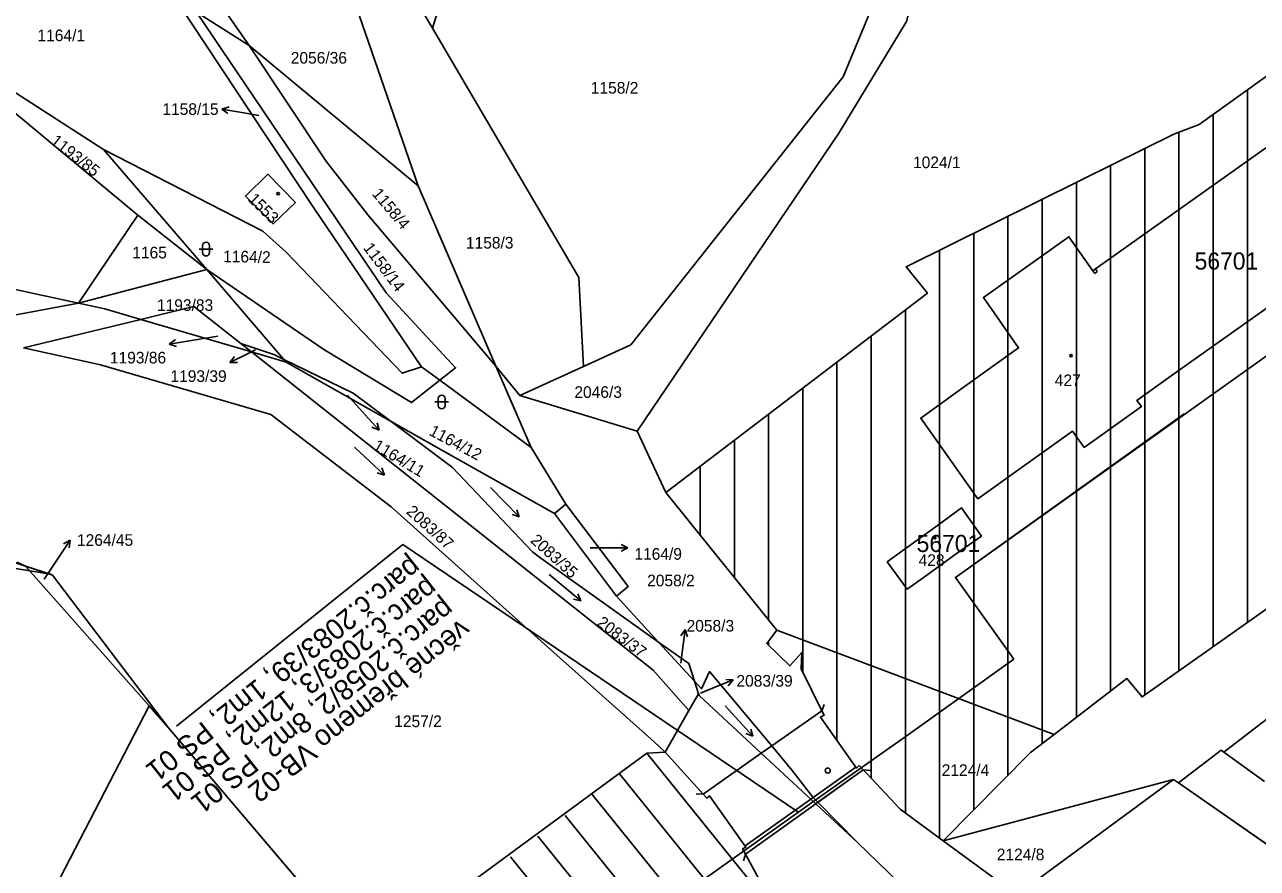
# Model space of a CAD drawing. Extents: x -794765 to -785424, y -1118958 to -1108731.
# Drawn here: x -792518 to -792337.7, y -1109962.1 to -1109838.8 of the extents above; entities that cross this region are included whole.
import ezdxf

# ---------------------------------------------------------------- set-up
doc = ezdxf.new("R2010")
doc.units = 0
for name, color, linetype in [('Level 66', 7, 'Continuous'), ('Level 75', 7, 'Continuous'), ('Level 76', 7, 'Continuous'), ('Level 77', 7, 'Continuous'), ('Level 78', 7, 'Continuous'), ('Level 79', 7, 'Continuous'), ('Level 80', 7, 'Continuous'), ('Level 81', 7, 'Continuous'), ('Vrstva 1', 7, 'Continuous'), ('Vrstva 53', 7, 'Continuous')]:
    doc.layers.add(name, color=color, linetype=linetype)

msp = doc.modelspace()

# ---------------------------------------------------------------- linework, layer by layer
at = {"layer": 'Level 66'}
for p, q in [((-792491.95, -1109871.12), (-792491.95, -1109872.12)), ((-792490.95, -1109872.12), (-792490.95, -1109871.12)), ((-792492.45, -1109871.62), (-792490.45, -1109871.62)), ((-792457.99, -1109893.95), (-792455.99, -1109893.95)), ((-792457.49, -1109893.45), (-792457.49, -1109894.45)), ((-792456.49, -1109894.45), (-792456.49, -1109893.45)), ((-792469.74, -1109900.54), (-792465.35, -1109904.63)), ((-792465.35, -1109904.63), (-792465.72, -1109903.6)), ((-792465.35, -1109904.63), (-792466.41, -1109904.33)), ((-792449.84, -1109906.43), (-792445.67, -1109910.75)), ((-792445.67, -1109910.75), (-792446.71, -1109910.39)), ((-792445.67, -1109910.75), (-792445.99, -1109909.7)), ((-792441.26, -1109919.17), (-792436.66, -1109923.03)), ((-792436.66, -1109923.03), (-792437.73, -1109922.78)), ((-792436.66, -1109923.03), (-792437.09, -1109922.01)), ((-792415.53, -1109938.35), (-792411.52, -1109942.81)), ((-792411.52, -1109942.81), (-792412.54, -1109942.42)), ((-792411.52, -1109942.81), (-792411.8, -1109941.75))]:
    msp.add_line(p, q, dxfattribs=at)
for centre, start, end in [((-792491.45, -1109871.12), 0, 180), ((-792491.45, -1109872.12), 180, 359.9879), ((-792456.99, -1109893.45), 0, 180), ((-792456.99, -1109894.45), 180, 359.9879)]:
    msp.add_arc(centre, 0.5, start, end, dxfattribs=at)
at = {"layer": 'Level 75'}
for p, q in [((-792470.06, -1109834.57), (-792460.44, -1109862.36)), ((-792458.34, -1109839.35), (-792461.61, -1109833.78)), ((-792501.44, -1109866.68), (-792535.33, -1109838.48)), ((-792485.15, -1109841.88), (-792492.83, -1109837.02)), ((-792460.44, -1109862.36), (-792485.15, -1109841.88)), ((-792506.45, -1109857.05), (-792491.34, -1109874.62)), ((-792460.44, -1109862.36), (-792449.06, -1109888.71)), ((-792510.07, -1109879.52), (-792501.44, -1109866.68)), ((-792491.34, -1109874.62), (-792501.44, -1109866.68)), ((-792551.16, -1109870.68), (-792510.07, -1109879.52)), ((-792510.07, -1109879.52), (-792491.34, -1109874.62)), ((-792491.34, -1109874.62), (-792480.06, -1109887.74)), ((-792518.11, -1109886.06), (-792500.99, -1109881.89)), ((-792500.99, -1109881.89), (-792484.82, -1109886.64)), ((-792486.38, -1109885.41), (-792484.82, -1109886.64)), ((-792484.82, -1109886.64), (-792479.72, -1109888.14)), ((-792479.72, -1109888.14), (-792480.06, -1109887.74)), ((-792479.72, -1109888.14), (-792464.39, -1109896.81)), ((-792459.92, -1109888.82), (-792457.26, -1109890.78)), ((-792449.06, -1109888.71), (-792445.59, -1109893)), ((-792449.06, -1109888.71), (-792443.92, -1109900.63)), ((-792445.59, -1109893), (-792436.24, -1109888.75)), ((-792457.26, -1109890.78), (-792443.92, -1109900.63)), ((-792445.59, -1109893), (-792428.41, -1109898.21)), ((-792428.41, -1109898.21), (-792424.2, -1109907.16)), ((-792443.92, -1109900.63), (-792438.83, -1109908.9)), ((-792407.99, -1109927.32), (-792424.2, -1109907.16)), ((-792438.83, -1109908.9), (-792440.51, -1109910.24)), ((-792440.51, -1109910.24), (-792431.42, -1109922.33)), ((-792519.12, -1109917.38), (-792517.82, -1109917.95)), ((-792499.77, -1109938.38), (-792517.82, -1109917.95)), ((-792431.42, -1109922.33), (-792425.28, -1109929.04)), ((-792407.99, -1109927.32), (-792367.46, -1109942.54)), ((-792425.28, -1109929.04), (-792420.03, -1109934.77)), ((-792420.03, -1109934.77), (-792419.43, -1109936.6)), ((-792419.43, -1109936.6), (-792420.84, -1109939.05)), ((-792525.39, -1109987.79), (-792499.77, -1109938.38)), ((-792499.77, -1109938.38), (-792496.95, -1109941.57)), ((-792420.84, -1109939.05), (-792424.33, -1109945.11)), ((-792496.95, -1109941.57), (-792468.07, -1109975.45)), ((-792394.9, -1109948.21), (-792395.36, -1109947.72)), ((-792383.68, -1109958.07), (-792350, -1109949.1)), ((-792350, -1109949.1), (-792372.92, -1109965.97)), ((-792349.29, -1109949.6), (-792350, -1109949.1)), ((-792349.29, -1109949.6), (-792300.79, -1109983.35)), ((-792372.92, -1109965.97), (-792383.68, -1109958.07))]:
    msp.add_line(p, q, dxfattribs=at)
for points in [[(-792436.24, -1109888.75), (-792429.34, -1109885.63), (-792398.28, -1109846.46), (-792394.13, -1109836.46), (-792388.49, -1109812.75), (-792381.95, -1109813.67)], [(-792485.15, -1109841.88), (-792494.43, -1109828.49), (-792506.9, -1109817.42)], [(-792444.99, -1109826.89), (-792455.12, -1109834.05), (-792456.58, -1109835.43), (-792457.64, -1109837.14), (-792458.34, -1109839.35)], [(-792386.68, -1109829.15), (-792389.02, -1109838.35), (-792398.94, -1109854.66), (-792428.41, -1109898.21)], [(-792459.92, -1109888.82), (-792475.83, -1109865.41), (-792495.87, -1109835.1)], [(-792535.33, -1109838.48), (-792529.02, -1109842.55), (-792506.45, -1109857.05)], [(-792492.83, -1109837.02), (-792465.09, -1109878), (-792454.96, -1109888.96), (-792457.26, -1109890.78)], [(-792458.34, -1109839.35), (-792436.95, -1109875.77), (-792436.24, -1109888.75)], [(-792424.2, -1109907.16), (-792385.97, -1109878.06), (-792389.09, -1109874.23), (-792363.55, -1109861.57), (-792349.96, -1109854.83), (-792346.23, -1109853.43), (-792326.43, -1109839.17)], [(-792485.15, -1109841.88), (-792473.92, -1109858.72), (-792467.78, -1109866.63), (-792449.06, -1109888.71)], [(-792350.32, -1109890.12), (-792310.53, -1109861.95), (-792321.58, -1109846.27), (-792361.41, -1109874.49), (-792361.79, -1109874.77), (-792365.28, -1109869.81), (-792377.79, -1109878.69), (-792372.64, -1109886.06), (-792380.76, -1109891.84), (-792386.94, -1109896.32), (-792378.6, -1109908.09), (-792372.63, -1109903.82), (-792364.77, -1109898.2), (-792363.05, -1109900.6), (-792354.69, -1109894.62), (-792355.34, -1109893.72), (-792350.32, -1109890.12)], [(-792506.45, -1109857.05), (-792483.14, -1109869.01), (-792479.72, -1109872.05), (-792462.76, -1109889.76), (-792459.92, -1109888.82)], [(-792478.36, -1109864.79), (-792482.43, -1109860.67), (-792485.69, -1109863.88), (-792481.62, -1109867.94), (-792478.36, -1109864.79)], [(-792510.07, -1109879.52), (-792529.74, -1109883.15), (-792549.88, -1109872.57), (-792551.16, -1109870.68)], [(-792491.34, -1109874.62), (-792474.22, -1109886.31), (-792461.4, -1109894.05), (-792457.26, -1109890.78)], [(-792510.07, -1109879.52), (-792506.25, -1109880.34), (-792500.99, -1109881.89)], [(-792500.99, -1109881.89), (-792498.62, -1109881.31), (-792493.21, -1109880), (-792486.38, -1109885.41)], [(-792367.46, -1109942.54), (-792356.82, -1109934.38), (-792354.59, -1109937.05), (-792274.06, -1109880.18), (-792264.32, -1109887.25)], [(-792480.06, -1109887.74), (-792481.52, -1109887.04), (-792486.38, -1109885.41)], [(-792424.33, -1109945.11), (-792425.94, -1109943.64), (-792440.58, -1109930.57), (-792464.4, -1109909.3), (-792481.97, -1109895.81), (-792506.88, -1109888.52), (-792518.11, -1109886.06)], [(-792484.82, -1109886.64), (-792426.08, -1109933.16), (-792420.84, -1109939.05)], [(-792464.39, -1109896.81), (-792469.93, -1109892.67), (-792480.06, -1109887.74)], [(-792464.39, -1109896.81), (-792455.39, -1109903.53), (-792443.7, -1109915.86), (-792442.51, -1109916.76), (-792425.28, -1109929.04)], [(-792440.51, -1109910.24), (-792453.09, -1109903.18), (-792457.76, -1109900.56), (-792464.39, -1109896.81)], [(-792431.42, -1109922.33), (-792429.71, -1109920.9), (-792438.83, -1109908.9)], [(-792386.62, -1109919.63), (-792381.57, -1109916.02), (-792378.09, -1109913.54), (-792380.99, -1109909.44), (-792384.51, -1109912), (-792389.55, -1109915.67), (-792391.84, -1109917.33), (-792388.96, -1109921.29), (-792386.62, -1109919.63)], [(-792517.82, -1109917.95), (-792513.88, -1109919.24), (-792496.95, -1109941.57)], [(-792395.36, -1109947.72), (-792395.96, -1109947.08), (-792396.36, -1109947.46), (-792401.63, -1109940.01), (-792401.09, -1109939.74), (-792401.42, -1109939.07), (-792404.43, -1109932.95), (-792404.35, -1109930.54), (-792406.09, -1109932.53), (-792409.46, -1109929.26), (-792407.99, -1109927.32)], [(-792425.28, -1109929.04), (-792420.88, -1109932.17), (-792420.03, -1109934.77)], [(-792325.83, -1109932.23), (-792337.77, -1109941.39), (-792342.64, -1109945.14), (-792343.04, -1109944.85), (-792349.29, -1109949.6)], [(-792420.03, -1109934.77), (-792419.01, -1109935.88), (-792417.84, -1109933.35), (-792408.74, -1109944.21), (-792405.73, -1109947.8), (-792402.71, -1109951.72), (-792401.99, -1109952.45), (-792396.21, -1109958.32)], [(-792396.21, -1109958.32), (-792402.3, -1109952.67), (-792410.26, -1109945.28), (-792419.34, -1109936.86), (-792419.43, -1109936.6)], [(-792383.68, -1109958.07), (-792370.89, -1109945.17), (-792367.46, -1109942.54)], [(-792424.33, -1109945.11), (-792427.01, -1109945.27), (-792468.07, -1109975.45)], [(-792424.33, -1109945.11), (-792418.77, -1109951.27), (-792418.22, -1109951.87), (-792417.83, -1109951.51), (-792412.51, -1109959), (-792413, -1109959.27), (-792412.59, -1109960.02), (-792408.62, -1109967.32)], [(-792383.68, -1109958.07), (-792389.98, -1109953.44), (-792394.9, -1109948.21)], [(-792396.21, -1109958.32), (-792390.22, -1109964.13), (-792343.17, -1110003.9), (-792342.46, -1110004.5), (-792325.49, -1110016.94)]]:
    msp.add_lwpolyline(points, dxfattribs=at)
at = {"layer": 'Level 77'}
for p, q in [((-792361.79, -1109874.77), (-792361.51, -1109875.17)), ((-792361.14, -1109874.88), (-792361.41, -1109874.49)), ((-792361.51, -1109875.17), (-792361.14, -1109874.88)), ((-792401.42, -1109939.07), (-792408.74, -1109944.21)), ((-792401.06, -1109938.14), (-792401.42, -1109939.07)), ((-792408.74, -1109944.21), (-792410.26, -1109945.28)), ((-792410.26, -1109945.28), (-792418.77, -1109951.27)), ((-792336.7, -1109949.39), (-792342.64, -1109945.14)), ((-792395.36, -1109947.72), (-792401.99, -1109952.45)), ((-792394.36, -1109947.82), (-792395.36, -1109947.72)), ((-792419.77, -1109951.22), (-792418.77, -1109951.27)), ((-792402.3, -1109952.67), (-792412.59, -1109960.02)), ((-792401.99, -1109952.45), (-792402.3, -1109952.67)), ((-792412.85, -1109960.99), (-792412.59, -1109960.02))]:
    msp.add_line(p, q, dxfattribs=at)
at = {"layer": 'Level 78'}
for p, q in [((-792339.2, -1109926.18), (-792339.2, -1109848.37)), ((-792344.2, -1109929.71), (-792344.2, -1109851.97)), ((-792349.2, -1109933.24), (-792349.2, -1109854.54)), ((-792354.2, -1109936.77), (-792354.2, -1109856.93)), ((-792359.2, -1109936.21), (-792359.2, -1109859.41)), ((-792364.2, -1109940.04), (-792364.2, -1109861.89)), ((-792369.2, -1109943.87), (-792369.2, -1109864.37)), ((-792374.2, -1109948.51), (-792374.2, -1109866.85)), ((-792379.2, -1109953.55), (-792379.2, -1109869.33)), ((-792384.2, -1109957.69), (-792384.2, -1109871.81)), ((-792389.2, -1109954.01), (-792389.2, -1109880.52)), ((-792394.2, -1109948.95), (-792394.2, -1109884.32)), ((-792399.2, -1109943.45), (-792399.2, -1109888.13)), ((-792404.2, -1109933.42), (-792404.2, -1109891.94)), ((-792409.2, -1109925.82), (-792409.2, -1109895.74)), ((-792414.2, -1109919.6), (-792414.2, -1109899.55)), ((-792419.2, -1109913.38), (-792419.2, -1109903.35)), ((-792409.2, -1109929.51), (-792409.2, -1109928.92)), ((-792408.62, -1109967.98), (-792427.01, -1109945.27)), ((-792411.49, -1109972.38), (-792430.99, -1109948.3)), ((-792415.7, -1109975.13), (-792434.97, -1109951.33)), ((-792419.91, -1109977.88), (-792438.95, -1109954.36)), ((-792424.11, -1109980.63), (-792442.93, -1109957.39)), ((-792428.32, -1109983.37), (-792446.91, -1109960.42))]:
    msp.add_line(p, q, dxfattribs=at)
at = {"layer": 'Level 79'}
for centre in [(-792480.9, -1109863.52), (-792364.98, -1109887.18), (-792384.9, -1109913.8)]:
    msp.add_circle(centre, 0.175, dxfattribs=at)
at = {"layer": 'Level 80'}
for p, q in [((-792489.15, -1109851.15), (-792488.07, -1109850.83)), ((-792486.19, -1109851.67), (-792489.15, -1109851.15)), ((-792489.15, -1109851.15), (-792488.25, -1109851.82)), ((-792483.75, -1109852.09), (-792486.19, -1109851.67)), ((-792496.82, -1109885.49), (-792495.91, -1109884.84)), ((-792493.86, -1109885.02), (-792496.82, -1109885.49)), ((-792496.82, -1109885.49), (-792495.76, -1109885.83)), ((-792489.73, -1109884.34), (-792493.86, -1109885.02)), ((-792485.28, -1109886.88), (-792487.98, -1109888.2)), ((-792487.98, -1109888.2), (-792487.3, -1109887.31)), ((-792484.22, -1109886.36), (-792485.28, -1109886.88)), ((-792487.98, -1109888.2), (-792486.86, -1109888.21)), ((-792470.75, -1109892.97), (-792468.16, -1109895.83)), ((-792468.16, -1109895.83), (-792466.15, -1109898.06)), ((-792466.15, -1109898.06), (-792467.19, -1109897.65)), ((-792466.15, -1109898.06), (-792466.45, -1109896.98)), ((-792512.98, -1109916.63), (-792511.3, -1109914.14)), ((-792511.3, -1109914.14), (-792512.28, -1109914.69)), ((-792511.3, -1109914.14), (-792511.45, -1109915.25)), ((-792435.28, -1109915.25), (-792432.77, -1109915.26)), ((-792432.77, -1109915.26), (-792429.77, -1109915.26)), ((-792429.77, -1109915.26), (-792430.77, -1109914.76)), ((-792429.77, -1109915.26), (-792430.77, -1109915.76)), ((-792515.1, -1109919.84), (-792512.98, -1109916.63)), ((-792421.4, -1109927.19), (-792422.02, -1109928.12)), ((-792421.77, -1109930.17), (-792421.4, -1109927.19)), ((-792421.4, -1109927.19), (-792421.03, -1109928.25)), ((-792422.01, -1109932.1), (-792421.77, -1109930.17)), ((-792419.16, -1109936.5), (-792417.14, -1109935.7)), ((-792417.14, -1109935.7), (-792414.36, -1109934.58)), ((-792414.36, -1109934.58), (-792415.47, -1109934.49)), ((-792414.36, -1109934.58), (-792415.1, -1109935.42))]:
    msp.add_line(p, q, dxfattribs=at)
at = {"layer": 'Level 81'}
for points in [[(-792610.32, -1109857.13), (-792582.04, -1109864.04), (-792579.07, -1109859.32), (-792575.21, -1109853.19), (-792559.98, -1109829.02), (-792558.4, -1109826.51), (-792555.44, -1109826.91), (-792551.53, -1109827.43), (-792544.7, -1109832.44), (-792535.33, -1109838.48), (-792529.02, -1109842.55), (-792506.45, -1109857.05), (-792483.14, -1109869.01), (-792479.72, -1109872.05), (-792462.76, -1109889.76), (-792459.92, -1109888.82), (-792457.26, -1109890.78), (-792443.92, -1109900.63), (-792438.83, -1109908.9), (-792429.71, -1109920.9), (-792431.42, -1109922.33), (-792425.28, -1109929.04), (-792420.88, -1109932.17)], [(-792329.62, -1109997.74), (-792372.92, -1109965.97), (-792383.68, -1109958.07), (-792389.98, -1109953.44), (-792394.9, -1109948.21), (-792395.36, -1109947.72), (-792395.96, -1109947.08), (-792396.36, -1109947.46), (-792401.63, -1109940.01), (-792401.09, -1109939.74), (-792401.42, -1109939.07), (-792404.43, -1109932.95), (-792404.35, -1109930.54), (-792406.09, -1109932.53), (-792409.46, -1109929.26), (-792407.99, -1109927.32), (-792424.2, -1109907.16), (-792385.97, -1109878.06), (-792389.09, -1109874.23), (-792363.55, -1109861.57), (-792349.96, -1109854.83), (-792346.23, -1109853.43), (-792326.43, -1109839.17)], [(-792553.51, -1109911.17), (-792543.66, -1109909.49), (-792517.82, -1109917.95), (-792514.21, -1109919.13)], [(-792553.51, -1109911.17), (-792527.45, -1109916.99), (-792517.2, -1109918.65), (-792514.21, -1109919.13)], [(-792514.21, -1109919.13), (-792513.88, -1109919.24), (-792496.95, -1109941.57), (-792468.07, -1109975.45), (-792484.01, -1109988.67), (-792537.18, -1110032.76), (-792547.64, -1110038.22), (-792570.38, -1110049.94), (-792575.7, -1110052.69), (-792590.28, -1110048.67), (-792603.7, -1110040.3), (-792614.54, -1110062.94), (-792642.43, -1110065.76), (-792643.78, -1110065.79), (-792664.24, -1110066.26), (-792680.77, -1110065.03), (-792722.38, -1110056.28), (-792723.35, -1110056.08)], [(-792420.88, -1109932.17), (-792420.03, -1109934.77), (-792419.01, -1109935.88), (-792417.84, -1109933.35), (-792408.74, -1109944.21), (-792405.73, -1109947.8), (-792402.71, -1109951.72), (-792401.99, -1109952.45), (-792396.21, -1109958.32), (-792390.22, -1109964.13), (-792343.17, -1110003.9), (-792342.46, -1110004.5), (-792325.49, -1110016.94), (-792320.64, -1110020.43), (-792321.4, -1110021.63), (-792321.36, -1110021.79), (-792318.97, -1110023.02), (-792307.95, -1110029.74), (-792289.1, -1110038.19), (-792276.39, -1110054.16)], [(-792325.83, -1109932.23), (-792337.77, -1109941.39), (-792342.64, -1109945.14), (-792343.04, -1109944.85), (-792349.29, -1109949.6), (-792300.79, -1109983.35)]]:
    msp.add_lwpolyline(points, dxfattribs=at)
for points in [[(-792380.76, -1109891.84), (-792372.64, -1109886.06), (-792377.79, -1109878.69), (-792365.28, -1109869.81), (-792361.79, -1109874.77), (-792361.41, -1109874.49), (-792321.58, -1109846.27), (-792310.53, -1109861.95), (-792350.32, -1109890.12), (-792355.34, -1109893.72), (-792354.69, -1109894.62), (-792363.05, -1109900.6), (-792364.77, -1109898.2), (-792372.63, -1109903.82), (-792378.6, -1109908.09), (-792386.94, -1109896.32)], [(-792389.55, -1109915.67), (-792384.51, -1109912), (-792380.99, -1109909.44), (-792378.09, -1109913.54), (-792381.57, -1109916.02), (-792386.62, -1109919.63), (-792388.96, -1109921.29), (-792391.84, -1109917.33)]]:
    msp.add_lwpolyline(points, close=True, dxfattribs=at)
at = {"layer": 'Vrstva 1'}
for p, q in [((-792348.43, -1109895.7), (-792381.88, -1109919.59)), ((-792462.67, -1109914.78), (-792495.76, -1109941.31)), ((-792404.92, -1109953.86), (-792462.67, -1109914.78)), ((-792381.88, -1109919.59), (-792373.33, -1109931.54)), ((-792373.33, -1109931.54), (-792389.4, -1109943.05)), ((-792389.4, -1109943.05), (-792401.43, -1109951.47)), ((-792396.44, -1109947.34), (-792412.63, -1109958.83)), ((-792396.36, -1109947.46), (-792395.96, -1109947.08)), ((-792395.96, -1109947.08), (-792395.36, -1109947.72)), ((-792401.43, -1109951.47), (-792421.14, -1109965.5)), ((-792402.3, -1109952.67), (-792412.59, -1109960.02)), ((-792412.51, -1109959), (-792413, -1109959.27)), ((-792413, -1109959.27), (-792412.59, -1109960.02))]:
    msp.add_line(p, q, dxfattribs=at)
msp.add_lwpolyline([(-792262.89, -1109847.12), (-792303.98, -1109875.73), (-792309.37, -1109867.98), (-792381.88, -1109919.59), (-792373.33, -1109931.54)], dxfattribs=at)
msp.add_lwpolyline([(-792396.44, -1109947.34), (-792396.36, -1109947.46), (-792395.96, -1109947.08), (-792395.36, -1109947.72), (-792402.3, -1109952.67), (-792412.59, -1109960.02), (-792413, -1109959.27), (-792412.51, -1109959), (-792412.63, -1109958.83)], close=True, dxfattribs=at)
msp.add_circle((-792400.55, -1109947.82), 0.375, dxfattribs=at)
msp.add_circle((-792400.55, -1109947.82), 0.375, dxfattribs=at)
at = {"layer": 'Vrstva 53'}
for points in [[(-792363.55, -1109861.57), (-792349.96, -1109854.83), (-792346.23, -1109853.43), (-792326.43, -1109839.17)], [(-792274.06, -1109880.18), (-792354.59, -1109937.05), (-792356.82, -1109934.38), (-792367.46, -1109942.54), (-792370.89, -1109945.17), (-792383.68, -1109958.07), (-792389.98, -1109953.44), (-792394.9, -1109948.21), (-792395.36, -1109947.72), (-792395.96, -1109947.08), (-792396.36, -1109947.46), (-792401.63, -1109940.01), (-792401.09, -1109939.74), (-792401.42, -1109939.07), (-792404.43, -1109932.95), (-792404.35, -1109930.54), (-792406.09, -1109932.53), (-792409.46, -1109929.26), (-792407.99, -1109927.32), (-792424.2, -1109907.16), (-792385.97, -1109878.06), (-792389.09, -1109874.23), (-792363.55, -1109861.57)], [(-792468.07, -1109975.45), (-792427.01, -1109945.27), (-792424.33, -1109945.11), (-792418.77, -1109951.27), (-792418.22, -1109951.87), (-792417.83, -1109951.51), (-792412.51, -1109959), (-792413, -1109959.27), (-792412.59, -1109960.02), (-792408.62, -1109967.32)]]:
    msp.add_lwpolyline(points, dxfattribs=at)
msp.add_lwpolyline([(-792440.51, -1109910.24), (-792438.83, -1109908.9), (-792429.71, -1109920.9), (-792431.42, -1109922.33)], close=True, dxfattribs=at)

# ---------------------------------------------------------------- texts
at = {"layer": 'Level 76'}
for s, p in [('1164/1', (-792516.09, -1109841.24)), ('2056/36', (-792479.06, -1109844.52)), ('1158/2', (-792435.19, -1109848.9)), ('1158/15', (-792497.83, -1109852.01)), ('1024/1', (-792388.08, -1109859.79)), ('1158/3', (-792453.45, -1109871.54)), ('1165', (-792502.23, -1109872.98)), ('1193/83', (-792498.62, -1109880.65)), ('1193/86', (-792505.5, -1109888.33)), ('1193/39', (-792496.65, -1109891.03)), ('427', (-792367.36, -1109891.64)), ('2046/3', (-792437.59, -1109893.36)), ('1264/45', (-792510.32, -1109914.98)), ('1164/9', (-792428.82, -1109917.01)), ('428', (-792387.26, -1109917.92)), ('2058/2', (-792426.95, -1109920.89)), ('2058/3', (-792421.19, -1109927.51)), ('2083/39', (-792413.9, -1109935.55)), ('1257/2', (-792463.93, -1109941.46)), ('2124/4', (-792383.89, -1109948.6)), ('2124/8', (-792375.83, -1109960.92))]:
    msp.add_text(s, height=1.7, dxfattribs=at).set_placement(p)
for s, rotation, p in [('1193/85', 322, (-792514.3, -1109856.08)), ('1553', 315, (-792485.42, -1109864.44)), ('1158/4', 310, (-792467.27, -1109863.58)), ('1158/14', 307, (-792468.55, -1109871.46)), ('1164/2', 359, (-792488.96, -1109873.52)), ('1164/12', 332, (-792458.97, -1109898.71)), ('1164/11', 329, (-792467.16, -1109900.77)), ('2083/87', 318, (-792462.29, -1109910.13)), ('2083/35', 318, (-792444.14, -1109914.35)), ('2083/37', 323, (-792434.43, -1109926.48))]:
    msp.add_text(s, height=1.7, rotation=rotation, dxfattribs=at).set_placement(p)
at = {"layer": 'Level 81'}
for p in [(-792346.91, -1109874.61), (-792387.55, -1109915.88)]:
    msp.add_text('56701', height=2.5, dxfattribs=at).set_placement(p)
at = {"layer": 'Vrstva 1'}
for s, p in [('parc.č.2083/39, 1m2, PS 01', (-792461.47, -1109916.42)), ('parc.č.2083/3, 12m2, PS 01', (-792459.06, -1109919.47)), ('parc.č.2058/2, 8m2, PS 01', (-792456.65, -1109922.52)), ('věcné břemeno VB-02', (-792454.24, -1109925.56))]:
    msp.add_text(s, height=3, rotation=218.3254, dxfattribs=at).set_placement(p)

doc.saveas('drawing.dxf')
